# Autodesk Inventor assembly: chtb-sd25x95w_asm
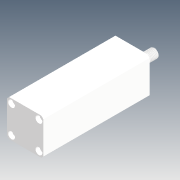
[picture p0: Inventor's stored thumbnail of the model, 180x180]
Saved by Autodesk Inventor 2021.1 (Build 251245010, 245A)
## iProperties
Company: Microsoft
Created: 2018-05
Part Number: chtb-sd25x95w_asm
Description: STEP AP214
Document SubType Name: Assembly
Designer: user
Title: chtb-sd25x95w_asm.STEP
Author: Windows
Revision Number: ÈÎºÎ
Sending System: SolidWorks 2015
Preprocessor: SwSTEP 2.0
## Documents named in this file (4)
- D:\Vault_2016\Projekty\Clamptek\Hydraulic\CHTB\CHTB-25\Inventor\chtb-sd25x95w\chtb-sd25x95w_asm.iam
- D:\Vault_2016\Projekty\Clamptek\Hydraulic\CHTB\CHTB-25\Inventor\chtb-sd25x95w\CHTB-25QG.ipt
- D:\Vault_2016\Projekty\Clamptek\Hydraulic\CHTB\CHTB-25\Inventor\chtb-sd25x95w\CHTB-SD25X95NBT.ipt
- D:\Vault_2016\Projekty\Clamptek\Hydraulic\CHTB\CHTB-25\Inventor\chtb-sd25x95w\CHTB-SD25X95WHSG.ipt
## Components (3 placed, 3 different names)
1. CHTB-25QG_1
2. CHTB-SD25X95NBT_2
3. CHTB-SD25X95WHSG_3
